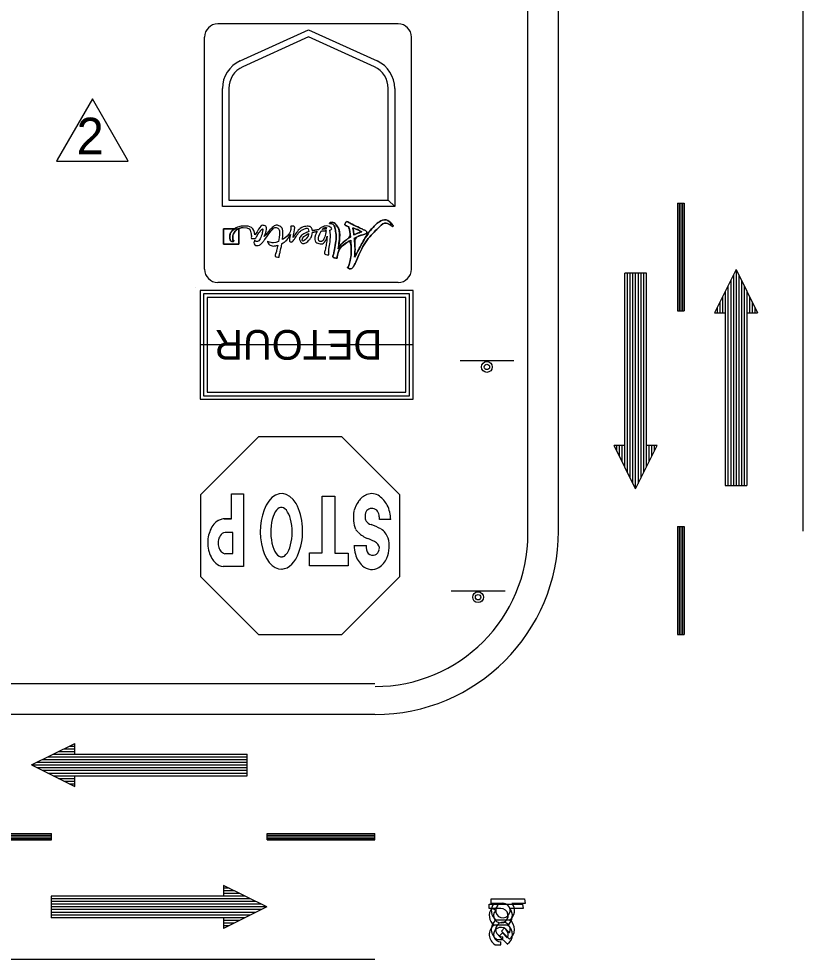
# Model space of a CAD drawing. Extents: x 1482 to 1692, y 225 to 494.
# Drawn here: x 1606.61 to 1637.63, y 314.22 to 351.41 of the extents above; entities that cross this region are included whole.
import ezdxf

# ---------------------------------------------------------------- set-up
doc = ezdxf.new("R2010")
doc.units = 0
for name, color, linetype in [('Level 17', 7, 'Continuous'), ('Level 2', 7, 'Continuous'), ('Level 53', 7, 'Continuous'), ('Level 60', 7, 'Continuous')]:
    doc.layers.add(name, color=color, linetype=linetype)

msp = doc.modelspace()

# ---------------------------------------------------------------- linework, layer by layer
at = {"layer": 'Level 17'}
for p, q in [((1613.585, 340.766), (1613.585, 340.766)), ((1613.585, 340.766), (1613.585, 340.766)), ((1613.585, 340.766), (1613.585, 340.766)), ((1613.585, 340.766), (1613.585, 340.766)), ((1622.206, 338.516), (1613.769, 338.516)), ((1626.193, 337.881), (1624.06, 337.881)), ((1615.02, 331.641), (1615.02, 332.621)), ((1615.02, 332.621), (1615.497, 332.621)), ((1615.497, 332.621), (1615.497, 329.747)), ((1618.605, 332.537), (1619.103, 332.537)), ((1618.605, 330.289), (1618.605, 332.537)), ((1619.103, 332.537), (1619.103, 330.277)), ((1621.179, 332.177), (1621.182, 332.175)), ((1615.02, 331.641), (1614.72, 331.641)), ((1614.734, 331.634), (1615.02, 331.641)), ((1621.322, 331.609), (1620.872, 331.609)), ((1615.077, 331.099), (1614.771, 331.099)), ((1615.077, 331.099), (1614.771, 331.099)), ((1615.077, 330.263), (1615.077, 331.099)), ((1615.077, 330.263), (1615.077, 331.099)), ((1618.101, 329.774), (1618.101, 330.289)), ((1618.101, 330.289), (1618.605, 330.289)), ((1619.865, 330.577), (1620.357, 330.577)), ((1614.765, 330.263), (1615.077, 330.263)), ((1614.765, 330.263), (1615.077, 330.263)), ((1617.044, 330.135), (1617.024, 330.131)), ((1619.103, 330.277), (1619.631, 330.277)), ((1619.631, 330.277), (1619.631, 329.774)), ((1615.497, 329.747), (1614.693, 329.747)), ((1617.024, 329.647), (1617.009, 329.645)), ((1619.631, 329.774), (1618.101, 329.774)), ((1625.844, 328.774), (1623.711, 328.774)), ((1625.295, 316.427), (1625.295, 316.599)), ((1625.295, 316.599), (1626.614, 316.599)), ((1626.614, 316.599), (1626.636, 316.427)), ((1625.214, 316.226), (1625.214, 316.398)), ((1625.214, 316.398), (1626.533, 316.398)), ((1625.673, 316.226), (1625.214, 316.226)), ((1625.754, 316.427), (1625.295, 316.427)), ((1625.315, 316.224), (1625.388, 316.224)), ((1625.396, 316.425), (1625.469, 316.425)), ((1626.555, 316.226), (1626.03, 316.226)), ((1626.636, 316.427), (1626.111, 316.427)), ((1626.533, 316.398), (1626.555, 316.226)), ((1625.941, 315.566), (1625.406, 315.566)), ((1625.941, 315.566), (1625.406, 315.566)), ((1626.022, 315.767), (1625.487, 315.767)), ((1626.022, 315.767), (1625.487, 315.767)), ((1625.817, 315.455), (1625.694, 315.331)), ((1626.01, 315.26), (1625.817, 315.455)), ((1625.736, 315.254), (1625.613, 315.13)), ((1625.613, 315.13), (1625.931, 314.812)), ((1625.694, 315.331), (1626.012, 315.013)), ((1625.929, 315.059), (1625.736, 315.254)), ((1625.754, 314.991), (1625.754, 315.104)), ((1625.451, 314.79), (1625.673, 314.79)), ((1625.532, 314.991), (1625.754, 314.991)), ((1625.673, 314.79), (1625.673, 314.903)), ((1625.931, 314.812), (1625.931, 314.812)), ((1626.012, 315.013), (1626.012, 315.013))]:
    msp.add_line(p, q, dxfattribs=at)
for points in [[(1613.775, 336.362), (1622.202, 336.362), (1622.202, 340.67), (1613.775, 340.67)], [(1613.916, 336.503), (1622.061, 336.503), (1622.061, 340.529), (1613.916, 340.529)], [(1614.057, 336.642), (1621.92, 336.642), (1621.92, 340.388), (1614.057, 340.388)], [(1613.808, 332.601), (1616.102, 334.895), (1619.368, 334.895), (1621.662, 332.601), (1621.662, 329.335), (1619.368, 327.043), (1616.102, 327.043), (1613.808, 329.335)]]:
    msp.add_lwpolyline(points, close=True, dxfattribs=at)
for points in [[(1625.388, 316.224), (1625.471, 316.144)], [(1625.469, 316.425), (1625.552, 316.345)]]:
    msp.add_lwpolyline(points, dxfattribs=at)
for centre, radius in [((1625.122, 337.642), 0.213), ((1625.122, 337.642), 0.107), ((1624.773, 328.535), 0.213), ((1624.773, 328.535), 0.107)]:
    msp.add_circle(centre, radius, dxfattribs=at)
for centre, radius, start, end in [((1620.686, 331.879), 0.782, 113.1413, 144.9906), ((1620.571, 332.144), 0.489, 52.0536, 112.7397), ((1620.238, 331.668), 1.07, 28.4154, 53.6553), ((1621.167, 331.556), 1.361, 145.5092, 163.2894), ((1619.82, 331.542), 1.502, 2.3841, 24.9519), ((1621.573, 331.677), 1.731, 171.247, 183.9864), ((1620.72, 331.743), 0.413, 146.253, 178.7323), ((1620.585, 331.74), 0.31, 95.4374, 134.0626), ((1620.56, 331.714), 0.335, 50.6966, 91.4573), ((1620.514, 331.745), 0.344, 6.8728, 42.7449), ((1620.192, 331.616), 0.685, 359.0172, 13.5172), ((1614.904, 330.91), 0.774, 138.2922, 158.6031), ((1614.904, 330.91), 0.774, 138.2922, 158.6031), ((1614.703, 331.132), 0.478, 115.3838, 142.6188), ((1614.846, 330.949), 0.706, 106.602, 119.8091), ((1614.704, 331.471), 0.166, 79.7909, 113.5419), ((1621.063, 331.68), 1.223, 185.9097, 201.9865), ((1620.624, 331.705), 0.319, 172.5761, 210.4776), ((1620.634, 331.742), 0.348, 214.2083, 254.1552), ((1618.55, 326.257), 5.521, 64.4624, 68.8312), ((1615.659, 330.606), 1.588, 158.3153, 168.6699), ((1614.837, 330.781), 0.325, 101.9191, 145.7868), ((1614.837, 330.781), 0.325, 101.9191, 145.7868), ((1618.449, 329.794), 2.053, 39.479, 43.426), ((1620.85, 331.943), 1.175, 226.2465, 247.9263), ((1620.502, 330.609), 0.762, 20.4481, 55.1107), ((1615.297, 330.701), 1.215, 169.7521, 182.7916), ((1615.297, 330.701), 1.215, 169.7521, 182.7916), ((1614.961, 330.676), 0.468, 170.3417, 195.2342), ((1614.961, 330.676), 0.468, 170.3417, 195.2342), ((1614.917, 330.733), 0.418, 146.5086, 177.0313), ((1614.917, 330.733), 0.418, 146.5086, 177.0313), ((1619.864, 329.266), 1.68, 57.9816, 70.979), ((1620.627, 330.484), 0.242, 344.131, 58.1476), ((1620.188, 330.577), 1.071, 354.8171, 15.9183), ((1615.593, 330.73), 1.512, 183.3903, 195.6597), ((1614.895, 330.501), 0.778, 193.0674, 213.762), ((1614.945, 330.619), 0.44, 188.6031, 214.217), ((1614.945, 330.619), 0.44, 188.6031, 214.217), ((1614.813, 330.535), 0.283, 215.1198, 259.3117), ((1614.813, 330.535), 0.283, 215.1198, 259.3117), ((1621.111, 330.598), 1.243, 180.6952, 197.1452), ((1620.746, 330.516), 0.405, 170.4412, 219.3244), ((1620.596, 330.446), 0.264, 293.8064, 352.2407), ((1620.037, 330.544), 1.219, 337.7332, 357.1392), ((1614.885, 330.429), 0.732, 209.2241, 228.5308), ((1614.885, 330.429), 0.732, 209.2241, 228.5308), ((1620.793, 330.457), 0.898, 194.564, 229.0063), ((1620.617, 330.468), 0.277, 227.3017, 289.0119), ((1620.371, 330.438), 0.87, 303.3662, 335.6734), ((1614.735, 330.22), 0.477, 224.8528, 265.0441), ((1620.571, 330.165), 0.532, 226.1369, 301.3987)]:
    msp.add_arc(centre, radius, start, end, dxfattribs=at)
for centre, major_axis, ratio, start_param, end_param in [((1616.997, 331.142), (0.01, 1.497), 0.558644, 4.129576, 6.939747), ((1616.997, 331.142), (0.01, 1.497), 0.558644, 0.656861, 3.168126), ((1616.997, 331.108), (-0.005, 0.977), 0.432619, 3.890436, 7.165085), ((1616.997, 331.108), (-0.005, 0.977), 0.432619, 0.881967, 3.190734), ((1616.997, 331.142), (0.01, 1.497), 0.558644, 3.185857, 4.129398), ((1616.997, 331.108), (-0.005, 0.977), 0.432619, 3.239639, 3.888884), ((1625.675, 315.939), (-0.46, 0), 0.999971, 5.612736, 7.226621), ((1625.756, 316.14), (-0.46, 0), 0.999971, 5.612736, 7.226621), ((1625.674, 315.94), (0.287, 0), 0.999971, 2.356342, 7.857549), ((1625.755, 316.141), (0.287, 0), 0.999971, 2.356342, 7.857549), ((1625.671, 315.938), (0.46, 0), 0.999971, 5.341225, 6.958912), ((1625.752, 316.139), (0.46, 0), 0.999971, 5.341225, 6.958912), ((1625.675, 315.193), (-0.46, 0), 0.999971, 5.33694, 7.34642), ((1625.756, 315.394), (-0.46, 0), 0.999971, 5.33694, 7.34642), ((1625.674, 315.191), (0.287, 0), 0.999971, 5.806109, 10.99129), ((1625.755, 315.392), (0.287, 0), 0.999971, 5.806109, 10.99129), ((1625.672, 315.193), (0.46, 0), 0.999971, 5.308365, 7.228665), ((1625.753, 315.394), (0.46, 0), 0.999971, 5.308365, 7.228665)]:
    msp.add_ellipse(centre, major_axis=major_axis, ratio=ratio, start_param=start_param, end_param=end_param, dxfattribs=at)
at = {"layer": 'Level 2'}
for p, q in [((1626.745, 331.052), (1626.745, 370.179)), ((1627.955, 331.153), (1627.955, 370.179)), ((1637.632, 331.153), (1637.632, 370.179)), ((1621.618, 351.209), (1614.476, 351.209)), ((1615.359, 349.744), (1618.068, 350.976)), ((1618.068, 350.976), (1620.777, 349.744)), ((1613.958, 341.504), (1613.958, 350.691)), ((1618.068, 350.695), (1615.465, 349.511)), ((1620.671, 349.511), (1618.068, 350.695)), ((1622.136, 341.504), (1622.136, 350.691)), ((1614.661, 343.99), (1614.661, 348.658)), ((1614.916, 348.658), (1614.916, 344.245)), ((1621.22, 344.245), (1621.22, 348.658)), ((1621.476, 348.658), (1621.476, 343.99)), ((1614.916, 344.245), (1621.22, 344.245)), ((1621.476, 343.99), (1621.22, 344.245)), ((1621.22, 344.245), (1621.476, 343.99)), ((1632.665, 344.125), (1632.665, 339.859)), ((1632.665, 344.125), (1632.921, 344.125)), ((1632.729, 344.125), (1632.729, 339.859)), ((1632.793, 344.125), (1632.793, 339.859)), ((1632.857, 344.125), (1632.857, 339.859)), ((1632.921, 344.125), (1632.921, 339.859)), ((1621.476, 343.99), (1614.661, 343.99)), ((1634.978, 341.492), (1634.125, 339.785)), ((1634.978, 341.492), (1634.978, 332.959)), ((1634.978, 341.492), (1635.831, 339.785)), ((1630.578, 334.529), (1630.578, 341.355)), ((1631.432, 341.355), (1630.578, 341.355)), ((1630.578, 333.675), (1630.578, 341.355)), ((1630.685, 333.462), (1630.685, 341.355)), ((1630.792, 333.249), (1630.792, 341.355)), ((1630.898, 333.035), (1630.898, 341.355)), ((1631.005, 332.822), (1631.005, 341.355)), ((1631.112, 333.035), (1631.112, 341.355)), ((1631.218, 333.249), (1631.218, 341.355)), ((1631.325, 333.462), (1631.325, 341.355)), ((1631.432, 334.529), (1631.432, 341.355)), ((1631.432, 333.675), (1631.432, 341.355)), ((1634.765, 341.065), (1634.765, 332.959)), ((1634.872, 341.278), (1634.872, 332.959)), ((1635.085, 341.278), (1635.085, 332.959)), ((1635.192, 341.065), (1635.192, 332.959)), ((1621.618, 340.986), (1614.476, 340.986)), ((1621.618, 340.986), (1614.476, 340.986)), ((1634.658, 340.852), (1634.658, 332.959)), ((1635.298, 340.852), (1635.298, 332.959)), ((1634.445, 340.425), (1634.445, 339.785)), ((1634.552, 340.638), (1634.552, 332.959)), ((1635.405, 340.638), (1635.405, 332.959)), ((1635.511, 340.425), (1635.511, 339.785)), ((1634.232, 339.998), (1634.232, 339.785)), ((1634.338, 340.212), (1634.338, 339.785)), ((1635.618, 340.212), (1635.618, 339.785)), ((1635.725, 339.998), (1635.725, 339.785)), ((1632.665, 339.859), (1632.921, 339.859)), ((1634.125, 339.785), (1634.552, 339.785)), ((1634.552, 339.785), (1634.552, 332.959)), ((1635.405, 339.785), (1635.405, 332.959)), ((1635.405, 339.785), (1635.831, 339.785)), ((1631.005, 332.822), (1630.152, 334.529)), ((1630.578, 334.529), (1630.152, 334.529)), ((1630.258, 334.315), (1630.258, 334.529)), ((1630.365, 334.102), (1630.365, 334.529)), ((1630.472, 333.889), (1630.472, 334.529)), ((1631.005, 332.822), (1631.858, 334.529)), ((1631.858, 334.529), (1631.432, 334.529)), ((1631.538, 333.889), (1631.538, 334.529)), ((1631.645, 334.102), (1631.645, 334.529)), ((1631.752, 334.315), (1631.752, 334.529)), ((1634.552, 332.959), (1635.405, 332.959)), ((1632.665, 331.326), (1632.665, 327.059)), ((1632.665, 331.326), (1632.921, 331.326)), ((1632.729, 331.326), (1632.729, 327.059)), ((1632.793, 331.326), (1632.793, 327.059)), ((1632.857, 331.326), (1632.857, 327.059)), ((1632.921, 331.326), (1632.921, 327.059)), ((1632.665, 327.059), (1632.921, 327.059)), ((1620.696, 325.105), (1559.225, 325.105)), ((1620.696, 323.894), (1559.225, 323.894)), ((1607.112, 321.901), (1608.818, 322.754)), ((1608.392, 322.541), (1608.818, 322.541)), ((1608.605, 322.648), (1608.818, 322.648)), ((1608.818, 322.328), (1608.818, 322.754)), ((1607.538, 322.114), (1615.645, 322.114)), ((1607.752, 322.221), (1615.645, 322.221)), ((1607.965, 322.328), (1615.645, 322.328)), ((1608.178, 322.434), (1608.818, 322.434)), ((1608.818, 322.328), (1615.645, 322.328)), ((1615.645, 321.474), (1615.645, 322.328)), ((1607.112, 321.901), (1615.645, 321.901)), ((1607.112, 321.901), (1608.818, 321.048)), ((1607.325, 322.008), (1615.645, 322.008)), ((1607.325, 321.794), (1615.645, 321.794)), ((1607.538, 321.688), (1615.645, 321.688)), ((1607.752, 321.581), (1615.645, 321.581)), ((1607.965, 321.474), (1615.645, 321.474)), ((1608.178, 321.368), (1608.818, 321.368)), ((1608.818, 321.474), (1615.645, 321.474)), ((1608.818, 321.048), (1608.818, 321.474)), ((1608.392, 321.261), (1608.818, 321.261)), ((1608.605, 321.154), (1608.818, 321.154)), ((1603.63, 319.189), (1607.897, 319.189)), ((1603.63, 319.125), (1607.897, 319.125)), ((1607.897, 318.933), (1607.897, 319.189)), ((1616.43, 319.189), (1620.696, 319.189)), ((1616.43, 318.933), (1616.43, 319.189)), ((1616.43, 319.125), (1620.696, 319.125)), ((1620.696, 318.933), (1620.696, 319.189)), ((1603.63, 319.061), (1607.897, 319.061)), ((1603.63, 318.997), (1607.897, 318.997)), ((1603.63, 318.933), (1607.897, 318.933)), ((1616.43, 319.061), (1620.696, 319.061)), ((1616.43, 318.997), (1620.696, 318.997)), ((1616.43, 318.933), (1620.696, 318.933)), ((1616.415, 316.284), (1614.708, 317.138)), ((1614.708, 317.138), (1614.708, 316.711)), ((1614.922, 317.031), (1614.708, 317.031)), ((1615.135, 316.924), (1614.708, 316.924)), ((1614.708, 316.711), (1607.882, 316.711)), ((1607.882, 316.711), (1607.882, 315.858)), ((1615.562, 316.711), (1607.882, 316.711)), ((1615.775, 316.604), (1607.882, 316.604)), ((1615.348, 316.818), (1614.708, 316.818)), ((1615.988, 316.498), (1607.882, 316.498)), ((1616.202, 316.391), (1607.882, 316.391)), ((1616.415, 316.284), (1607.882, 316.284)), ((1616.202, 316.178), (1607.882, 316.178)), ((1616.415, 316.284), (1614.708, 315.431)), ((1615.988, 316.071), (1607.882, 316.071)), ((1615.775, 315.964), (1607.882, 315.964)), ((1614.708, 315.858), (1607.882, 315.858)), ((1615.562, 315.858), (1607.882, 315.858)), ((1614.708, 315.858), (1614.708, 315.431)), ((1615.348, 315.751), (1614.708, 315.751)), ((1615.135, 315.644), (1614.708, 315.644)), ((1614.922, 315.538), (1614.708, 315.538)), ((1559.225, 314.218), (1620.696, 314.218))]:
    msp.add_line(p, q, dxfattribs=at)
for centre, radius, start, end in [((1614.476, 350.691), 0.518, 90, 180), ((1621.618, 350.691), 0.518, 360, 90), ((1615.853, 348.658), 1.193, 114.4568, 180), ((1620.283, 348.658), 1.193, 360, 65.5432), ((1615.853, 348.658), 0.937, 114.4568, 180), ((1620.283, 348.658), 0.937, 360, 65.5432), ((1614.476, 341.504), 0.518, 180, 270), ((1621.618, 341.504), 0.518, 270, 360), ((1620.697, 331.153), 7.258, 270, 360), ((1620.697, 331.052), 6.048, 270, 360)]:
    msp.add_arc(centre, radius, start, end, dxfattribs=at)
at = {"layer": 'Level 53'}
msp.add_line((1615.138, 343.101), (1615.288, 343.101), dxfattribs=at)
msp.add_lwpolyline([(1615.138, 343.101), (1614.698, 343.101), (1614.698, 342.493), (1615.306, 342.493), (1615.306, 343.101), (1615.288, 343.101)], dxfattribs=at)
for points, degree in [([(1618.951, 343.322), (1619.016, 343.312), (1619.102, 343.223), (1619.128, 343.077), (1619.174, 342.813), (1619.147, 342.553), (1619.069, 342.166), (1619.055, 342.092), (1619.005, 341.965), (1619.164, 341.941), (1619.214, 341.933), (1619.188, 341.958), (1619.202, 342.025), (1619.263, 342.314), (1619.499, 342.522), (1619.736, 342.661), (1619.761, 342.331), (1619.751, 341.964), (1619.689, 341.739), (1619.636, 341.549), (1619.574, 341.584), (1619.651, 341.544), (1619.733, 341.502), (1619.82, 341.558), (1619.891, 341.699), (1619.962, 341.84), (1620.288, 342.608), (1620.809, 343.126), (1621.076, 343.391), (1621.317, 343.255), (1621.365, 343.214), (1621.405, 343.181), (1621.419, 343.232), (1621.37, 343.284), (1621.155, 343.517), (1620.84, 343.384), (1620.725, 343.269), (1620.408, 342.952), (1620.039, 342.27), (1619.89, 341.98), (1619.904, 342.143), (1619.909, 342.417), (1619.878, 342.737), (1620.04, 342.816), (1620.184, 342.862), (1620.253, 342.88), (1620.326, 342.899), (1620.372, 342.929), (1620.374, 342.964), (1620.375, 343.001), (1620.325, 343.033), (1620.254, 343.067), (1620.126, 343.127), (1619.752, 343.304), (1619.66, 343.358), (1619.581, 343.403), (1619.542, 343.368), (1619.519, 343.318), (1619.488, 343.254), (1619.572, 343.217), (1619.653, 343.192), (1619.685, 343.084), (1619.709, 342.938), (1619.726, 342.777), (1619.536, 342.66), (1619.349, 342.504), (1619.241, 342.309), (1619.268, 342.472), (1619.338, 343.026), (1619.163, 343.26), (1619.125, 343.311), (1619.039, 343.368), (1618.956, 343.359), (1618.917, 343.356), (1618.898, 343.33), (1618.902, 343.322), (1618.906, 343.314), (1618.928, 343.325), (1618.951, 343.322)], 3), ([(1619.241, 342.309), (1619.268, 342.472), (1619.338, 343.026), (1619.163, 343.26), (1619.125, 343.311), (1619.039, 343.368), (1618.956, 343.359), (1618.917, 343.356), (1618.898, 343.33), (1618.902, 343.322), (1618.906, 343.314), (1618.928, 343.325), (1618.951, 343.322)], 3), ([(1618.951, 343.322), (1619.016, 343.312), (1619.102, 343.223), (1619.128, 343.077), (1619.174, 342.813), (1619.147, 342.553), (1619.069, 342.166), (1619.055, 342.092), (1619.005, 341.965), (1619.164, 341.941), (1619.214, 341.933), (1619.188, 341.958), (1619.202, 342.025), (1619.263, 342.314), (1619.499, 342.522), (1619.736, 342.661)], 3), ([(1619.878, 342.737), (1620.04, 342.816), (1620.184, 342.862), (1620.253, 342.88), (1620.326, 342.899), (1620.372, 342.929), (1620.374, 342.964), (1620.375, 343.001), (1620.325, 343.033), (1620.254, 343.067), (1620.126, 343.127), (1619.752, 343.304), (1619.66, 343.358), (1619.581, 343.403), (1619.542, 343.368), (1619.519, 343.318), (1619.488, 343.254), (1619.572, 343.217), (1619.653, 343.192)], 3), ([(1619.736, 342.661), (1619.761, 342.331), (1619.751, 341.964), (1619.689, 341.739), (1619.636, 341.549), (1619.574, 341.584), (1619.651, 341.544), (1619.733, 341.502), (1619.82, 341.558), (1619.891, 341.699), (1619.962, 341.84), (1620.288, 342.608), (1620.809, 343.126), (1621.076, 343.391), (1621.317, 343.255), (1621.365, 343.214), (1621.405, 343.181), (1621.419, 343.232), (1621.37, 343.284), (1621.155, 343.517), (1620.84, 343.384), (1620.725, 343.269), (1620.408, 342.952), (1620.039, 342.27), (1619.89, 341.98)], 3), ([(1615.306, 342.493), (1615.306, 342.493), (1615.306, 343.101), (1615.306, 343.101), (1615.306, 343.101), (1615.288, 343.101), (1615.288, 343.101), (1615.156, 343.022), (1615.068, 342.871), (1615.068, 342.747), (1615.068, 342.639), (1615.125, 342.645), (1615.118, 342.63), (1615.1, 342.587), (1614.965, 342.611), (1614.958, 342.763), (1614.951, 342.891), (1615.018, 343.016), (1615.138, 343.101), (1615.138, 343.101), (1614.698, 343.101), (1614.698, 343.101), (1614.698, 343.101), (1614.698, 342.493), (1614.698, 342.493), (1614.698, 342.493), (1615.306, 342.493), (1615.306, 342.493)], 3), ([(1615.288, 343.101), (1615.156, 343.022), (1615.068, 342.871), (1615.068, 342.747), (1615.068, 342.639), (1615.125, 342.645), (1615.118, 342.63), (1615.1, 342.587), (1614.965, 342.611), (1614.958, 342.763), (1614.951, 342.891), (1615.018, 343.016), (1615.138, 343.101)], 3), ([(1615.949, 342.87), (1615.935, 342.995), (1615.851, 343.211), (1615.514, 343.211), (1615.362, 343.211), (1615.234, 343.169), (1615.138, 343.101)], 3), ([(1615.288, 343.101), (1615.344, 343.134), (1615.408, 343.155), (1615.476, 343.155)], 2), ([(1615.476, 343.155), (1615.726, 343.155), (1615.79, 342.961), (1615.802, 342.865), (1615.81, 342.801), (1615.796, 342.709), (1615.907, 342.721), (1615.984, 342.73), (1616.054, 342.88), (1616.151, 343.007), (1616.235, 343.115), (1616.273, 343.105), (1616.253, 343.012), (1616.229, 342.895), (1616.132, 342.621), (1616.02, 342.601), (1615.969, 342.592), (1615.95, 342.682), (1615.926, 342.625), (1615.903, 342.569), (1615.924, 342.446), (1616.04, 342.446), (1616.121, 342.446), (1616.218, 342.532), (1616.297, 342.629), (1616.367, 342.714), (1616.717, 343.23), (1616.864, 343.119), (1616.933, 343.067), (1616.927, 342.855), (1616.884, 342.605)], 3), ([(1616.317, 342.797), (1616.396, 342.973), (1616.44, 343.198), (1616.322, 343.233), (1616.185, 343.273), (1616.076, 343.045), (1615.949, 342.87)], 3), ([(1617.035, 342.683), (1617.063, 342.918), (1617.053, 343.129), (1616.946, 343.196), (1616.75, 343.319), (1616.471, 342.995), (1616.317, 342.797)], 3), ([(1617.462, 342.761), (1617.476, 342.907), (1617.571, 343.227), (1617.408, 343.21), (1617.345, 343.204), (1617.372, 343.194), (1617.368, 343.139), (1617.355, 342.946), (1617.194, 342.783), (1617.035, 342.683)], 3), ([(1617.349, 342.881), (1617.334, 342.805), (1617.31, 342.722), (1617.309, 342.666), (1617.307, 342.606), (1617.348, 342.593), (1617.363, 342.589), (1617.398, 342.579), (1617.439, 342.596), (1617.481, 342.654), (1617.577, 342.79), (1617.699, 343.004), (1617.884, 343.094), (1618.017, 343.159), (1618.075, 343.094), (1618.078, 342.994)], 3), ([(1618.22, 343.028), (1618.207, 343.135), (1618.137, 343.217), (1617.975, 343.202), (1617.744, 343.181), (1617.539, 342.897), (1617.462, 342.761)], 3), ([(1618.078, 342.994), (1618.052, 342.986), (1618.029, 342.977), (1618.009, 342.969), (1617.768, 342.862), (1617.685, 342.701), (1617.747, 342.603), (1617.805, 342.51), (1617.971, 342.538), (1618.102, 342.676), (1618.166, 342.744), (1618.216, 342.861), (1618.222, 342.968)], 3), ([(1618.462, 343.067), (1618.381, 343.056), (1618.297, 343.043), (1618.22, 343.028)], 2), ([(1618.222, 342.968), (1618.277, 342.98), (1618.341, 342.99), (1618.413, 343)], 2), ([(1618.413, 343), (1618.299, 342.817), (1618.309, 342.569), (1618.475, 342.527), (1618.666, 342.478), (1618.763, 342.665), (1618.805, 342.82)], 3), ([(1618.764, 343.035), (1618.738, 342.84), (1618.636, 342.569), (1618.51, 342.612), (1618.437, 342.638), (1618.475, 342.866), (1618.569, 343.018)], 3), ([(1618.908, 343.052), (1618.976, 343.074), (1619.004, 343.126), (1618.916, 343.18), (1618.856, 343.217), (1618.722, 343.23), (1618.587, 343.163), (1618.539, 343.14), (1618.497, 343.106), (1618.462, 343.067)], 3), ([(1618.569, 343.018), (1618.63, 343.024), (1618.695, 343.03), (1618.764, 343.035)], 2), ([(1618.617, 343.084), (1618.651, 343.121), (1618.689, 343.146), (1618.729, 343.153)], 2), ([(1618.769, 343.096), (1618.735, 343.094), (1618.681, 343.09), (1618.617, 343.084)], 2), ([(1618.805, 342.82), (1618.792, 342.665), (1618.767, 342.476), (1618.732, 342.301), (1618.717, 342.227), (1618.667, 342.1), (1618.827, 342.076), (1618.877, 342.068), (1618.869, 342.092), (1618.865, 342.16), (1618.859, 342.252), (1618.961, 342.808), (1618.908, 343.052)], 3), ([(1618.729, 343.153), (1618.751, 343.156), (1618.77, 343.156), (1618.784, 343.153)], 2), ([(1618.784, 343.153), (1618.775, 343.145), (1618.77, 343.135), (1618.77, 343.121), (1618.77, 343.113), (1618.77, 343.105), (1618.769, 343.096)], 3), ([(1619.653, 343.192), (1619.685, 343.084), (1619.709, 342.938), (1619.726, 342.777)], 2), ([(1619.866, 342.856), (1619.85, 342.985), (1619.834, 343.079), (1619.815, 343.148)], 2), ([(1619.815, 343.148), (1619.898, 343.118), (1620.016, 343.07), (1620.17, 342.991)], 2), ([(1620.17, 342.991), (1620.086, 342.961), (1619.979, 342.916), (1619.866, 342.856), (1619.85, 342.985), (1619.834, 343.079), (1619.815, 343.148), (1619.898, 343.118), (1620.016, 343.07), (1620.17, 342.991)], 3), ([(1620.17, 342.991), (1620.086, 342.961), (1619.979, 342.916), (1619.866, 342.856)], 2), ([(1616.884, 342.605), (1616.709, 342.538), (1616.564, 342.56), (1616.482, 342.599), (1616.442, 342.619), (1616.436, 342.616), (1616.454, 342.571), (1616.479, 342.506), (1616.619, 342.403), (1616.838, 342.45), (1616.844, 342.452), (1616.849, 342.453), (1616.854, 342.454)], 3), ([(1617.012, 342.519), (1617.141, 342.593), (1617.261, 342.717), (1617.349, 342.881)], 2), ([(1617.95, 342.689), (1617.869, 342.614), (1617.829, 342.619), (1617.818, 342.639), (1617.795, 342.683), (1617.89, 342.836), (1618.072, 342.92)], 3), ([(1618.072, 342.92), (1618.057, 342.837), (1618.013, 342.747), (1617.95, 342.689)], 2), ([(1619.726, 342.777), (1619.536, 342.66), (1619.349, 342.504), (1619.241, 342.309)], 2), ([(1619.89, 341.98), (1619.904, 342.143), (1619.909, 342.417), (1619.878, 342.737)], 2), ([(1616.854, 342.454), (1616.836, 342.373), (1616.816, 342.291), (1616.794, 342.211), (1616.773, 342.137), (1616.713, 342.01), (1616.87, 341.986), (1616.92, 341.978), (1616.899, 342.002), (1616.915, 342.07), (1616.946, 342.195), (1616.984, 342.356), (1617.012, 342.519)], 3)]:
    msp.add_open_spline(points, degree=degree, dxfattribs=at)
at = {"layer": 'Level 60'}
for points in [[(1609.52, 348.253), (1608.127, 345.828)], [(1610.914, 345.828), (1609.52, 348.253)], [(1608.127, 345.828), (1608.101, 345.783), (1610.94, 345.783), (1610.914, 345.828)]]:
    msp.add_lwpolyline(points, dxfattribs=at)

# ---------------------------------------------------------------- texts
at = {"layer": 'Level 17'}
msp.add_text('DETOUR', height=1.1758, rotation=180, dxfattribs=at).set_placement((1620.981, 339.104))
at = {"layer": 'Level 60'}
msp.add_text('2', height=1.448, rotation=360, dxfattribs=at).set_placement((1608.893, 346.052))

doc.saveas('drawing.dxf')
